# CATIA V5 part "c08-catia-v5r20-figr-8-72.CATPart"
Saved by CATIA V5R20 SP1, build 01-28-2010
Part number: Part1
Bounding box of the stored display mesh (mm): x -81.893 to 81.893, y -175.508 to 175.508, z -50 to 146
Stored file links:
  D:\v5_r20\psrt_files_downloaded\c08-catia-v5r20-prt\c08-catia-v5r20-figr-8-72.CATPart
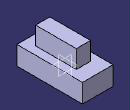
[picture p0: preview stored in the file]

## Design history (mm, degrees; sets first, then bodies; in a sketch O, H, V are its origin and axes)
Body1 (main body)
  Sketch1 on xy-plane, origin (0, 0, 0), H (1, 0, 0), V (0, 1, 0)
    line L1 (-81.8929, 175.5076) -> (81.8929, 175.5076)
    line L2 (81.8929, 175.5076) -> (81.8929, -175.5076)
    line L3 (81.8929, -175.5076) -> (-81.8929, -175.5076)
    line L4 (-81.8929, -175.5076) -> (-81.8929, 175.5076)
    axis line L5 (81.8929, -175.5076) -> (-81.8929, 175.5076)
    horizontal: L1 H, L3 H
    vertical: L2 V, L4 V
    midpoint: O L5
  Pad1: profile Sketch1, direction (0, 0, 1), length 50, mirrored extent
  Body2
    Sketch2 on xy-plane, origin (0, 0, 0), H (1, 0, 0), V (0, 1, 0)
      line L1 (-37.4906, 99.3013) -> (38.4681, 99.3013)
      line L2 (38.4681, 99.3013) -> (38.4681, -118.5305)
      line L3 (38.4681, -118.5305) -> (-37.4906, -118.5305)
      line L4 (-37.4906, -118.5305) -> (-37.4906, 99.3013)
      horizontal: L1 H, L3 H
      vertical: L2 V, L4 V
    Pad2: profile Sketch2, direction (0, 0, 1), length 146, opposite side length 150
  Trim1: tool Body2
